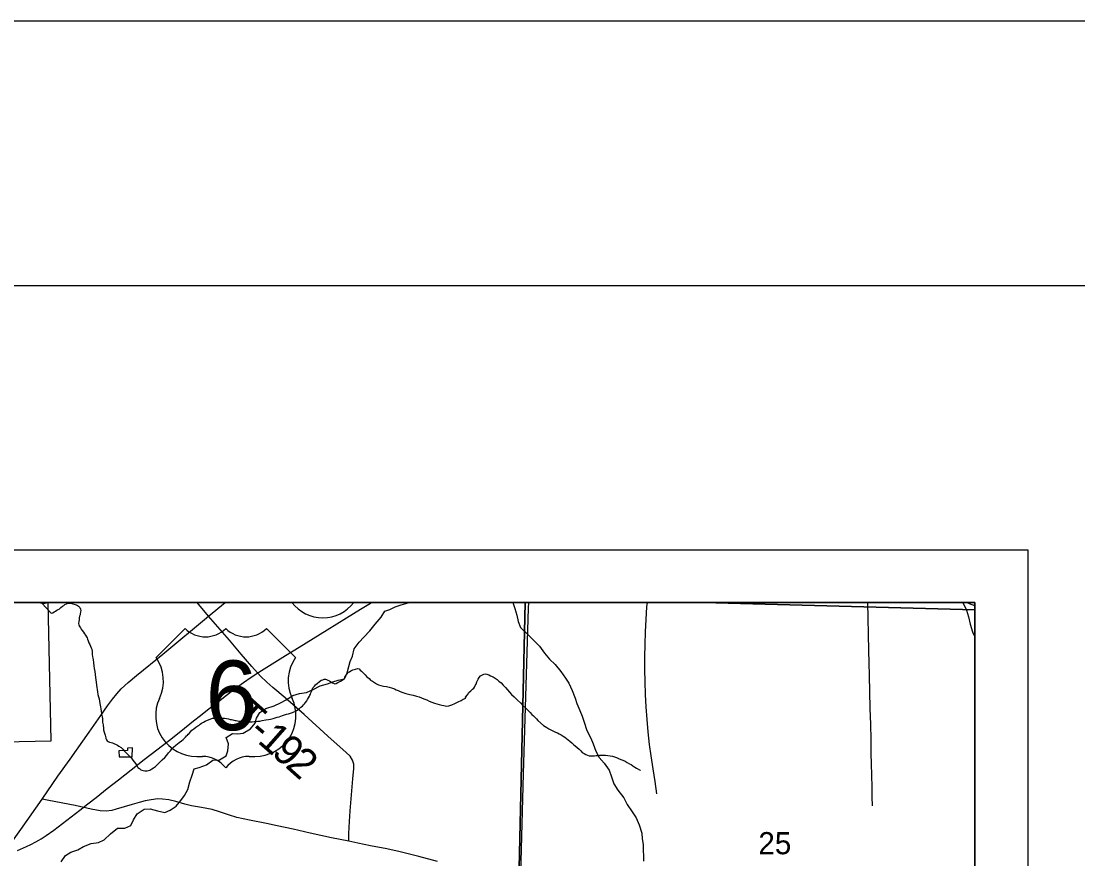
# Model space of a CAD drawing. Extents: x -6.1 to 38, y -7.7 to 22.
# Drawn here: x 7.096 to 9.095, y 20.415 to 22 of the extents above; entities that cross this region are included whole.
import ezdxf

# ---------------------------------------------------------------- set-up
doc = ezdxf.new("R2010")
doc.units = 0
for name, color, linetype in [('GM_X_Corporation', 7, 'Continuous'), ('GM_X_County_Road', 7, 'Continuous'), ('GM_X_Minor_Lake', 7, 'Continuous'), ('GM_X_Minor_River', 7, 'Continuous'), ('GM_X_Section_Text', 7, 'Continuous'), ('GM_X_Township_Road', 7, 'Continuous'), ('GM_X_Township_Road_Text', 7, 'Continuous'), ('GM_X_Unincorporated_Text', 7, 'Continuous'), ('GM_X_US_Location', 7, 'Continuous'), ('GM_X_US_Route', 7, 'Continuous'), ('GM_X_US_Shield', 7, 'Continuous'), ('SH_Border', 7, 'Continuous'), ('SH_Cut_Line', 7, 'Continuous'), ('SH_Data', 7, 'Continuous')]:
    doc.layers.add(name, color=color, linetype=linetype)

msp = doc.modelspace()

# ---------------------------------------------------------------- linework, layer by layer
at = {"layer": 'GM_X_Corporation'}
for points in [[(6.8881, 19.9366), (7.1749, 19.9235), (7.2362, 19.921), (8.0266, 19.8892), (8.0368, 20.3421), (8.0494, 20.9), (3.3101, 20.9)], [(6.9716, 20.6348), (7.153, 20.6384), (7.1472, 20.9), (4.3765, 20.9)]]:
    msp.add_lwpolyline(points, dxfattribs=at)
for points in [[(8.9, 19.5365), (8.9, 20.9), (6.9663, 20.9), (6.9744, 20.3805), (6.9756, 20.3051), (6.9766, 20.2418), (6.9774, 20.1931), (6.9933, 19.4733), (8.7731, 19.5323), (8.7757, 19.5324)], [(8.9, 19.8713), (8.9, 20.9), (8.0494, 20.9), (8.0368, 20.3421), (8.0266, 19.8892), (8.5381, 19.8802)], [(8.3868, 20.9), (8.0556, 20.9), (8.0552, 20.8892), (8.0457, 20.5759), (8.0276, 19.8894), (8.2637, 19.8849), (8.8507, 19.8735), (8.9, 19.8725), (8.9, 20.886)], [(8.9, 20.886), (8.9, 20.9), (8.3868, 20.9)]]:
    msp.add_lwpolyline(points, close=True, dxfattribs=at)
at = {"layer": 'GM_X_County_Road'}
for points in [[(7.1358, 20.5281), (7.1657, 20.5715), (7.1887, 20.6039), (7.2245, 20.6548), (7.2466, 20.6864), (7.2593, 20.7049), (7.2688, 20.717), (7.277, 20.7276), (7.2855, 20.7371), (7.2983, 20.7488), (7.314, 20.7618), (7.3639, 20.8023), (7.4505, 20.8741), (7.4822, 20.9)], [(6.7211, 20.0483), (6.7285, 20.0608), (6.7342, 20.0704), (6.7392, 20.076), (6.7582, 20.0915), (6.796, 20.1213), (6.838, 20.1539), (6.8672, 20.1774), (6.8837, 20.1917), (6.8958, 20.2039), (6.9054, 20.2146), (6.9181, 20.2305), (6.9463, 20.2673), (6.9666, 20.2941), (7.031, 20.3802), (7.0658, 20.4289), (7.0953, 20.4709), (7.1358, 20.5281)], [(7.8836, 20.41), (7.8484, 20.4198), (7.8132, 20.4287), (7.7876, 20.4341), (7.7566, 20.4401), (7.7327, 20.4446), (7.7162, 20.4484), (7.6832, 20.4552), (7.6426, 20.4637), (7.6106, 20.4711), (7.5806, 20.4774), (7.5601, 20.4818), (7.5283, 20.4881), (7.5038, 20.4933), (7.4881, 20.4983), (7.4716, 20.5043), (7.4573, 20.5084), (7.437, 20.5124), (7.4186, 20.5153), (7.4056, 20.5189), (7.3889, 20.5237), (7.3752, 20.5268), (7.3637, 20.5284), (7.3545, 20.5286), (7.3421, 20.527), (7.3309, 20.525), (7.3192, 20.5219), (7.3059, 20.5182), (7.2907, 20.5133), (7.2761, 20.5092), (7.2675, 20.5068), (7.257, 20.5052), (7.2457, 20.5061), (7.2286, 20.5092), (7.1985, 20.5158), (7.1488, 20.5254), (7.1358, 20.5281)]]:
    msp.add_lwpolyline(points, dxfattribs=at)
at = {"layer": 'GM_X_Minor_Lake'}
for points in [[(7.3067, 20.6251), (7.2976, 20.6247), (7.2973, 20.6201), (7.281, 20.6193), (7.2814, 20.6083)], [(7.2814, 20.6083), (7.306, 20.6084), (7.3067, 20.6251)]]:
    msp.add_lwpolyline(points, dxfattribs=at)
at = {"layer": 'GM_X_Minor_River'}
for points in [[(7.1318, 20.9), (7.133, 20.8997), (7.1353, 20.8989), (7.138, 20.8986), (7.1414, 20.8991), (7.1467, 20.8999), (7.147, 20.9)], [(7.1353, 20.8989), (7.1527, 20.8802), (7.1558, 20.8807), (7.1584, 20.8822), (7.161, 20.8838), (7.1637, 20.8854), (7.1663, 20.8866), (7.1682, 20.8874), (7.1715, 20.8908), (7.1742, 20.8932), (7.1768, 20.8947), (7.179, 20.8963), (7.1817, 20.8975), (7.1843, 20.8987), (7.1873, 20.8991), (7.1896, 20.8988), (7.1919, 20.8984), (7.2003, 20.8959), (7.2026, 20.8944), (7.2045, 20.8933), (7.2072, 20.8907), (7.2084, 20.8877), (7.2089, 20.8847), (7.2085, 20.8824), (7.2078, 20.8789), (7.2075, 20.8767), (7.2068, 20.8744), (7.2061, 20.8709), (7.2058, 20.8671), (7.2051, 20.8641), (7.2047, 20.8606), (7.2052, 20.858), (7.206, 20.8561), (7.2071, 20.8542), (7.2083, 20.8523), (7.2099, 20.8497), (7.2118, 20.8471), (7.2138, 20.8441), (7.2161, 20.8411), (7.2177, 20.8381), (7.22, 20.8354), (7.2208, 20.8332), (7.2216, 20.8305), (7.2232, 20.8275), (7.2244, 20.8241), (7.226, 20.8207), (7.2276, 20.8173), (7.2287, 20.8143), (7.2296, 20.8117), (7.2304, 20.8075), (7.2305, 20.8025), (7.2313, 20.7976), (7.2322, 20.7923), (7.2327, 20.7862), (7.2335, 20.7805), (7.2344, 20.7752), (7.2352, 20.7696), (7.2361, 20.7639), (7.2366, 20.7582), (7.2374, 20.754), (7.2392, 20.7396), (7.2396, 20.7358), (7.2405, 20.7312), (7.241, 20.7263), (7.2422, 20.7218), (7.2434, 20.7176), (7.2442, 20.7134), (7.2451, 20.7089), (7.2459, 20.7059), (7.2463, 20.7028), (7.2471, 20.699), (7.2476, 20.6945), (7.2481, 20.6899), (7.2489, 20.6865), (7.2493, 20.6839), (7.2498, 20.6805), (7.2498, 20.6782), (7.2502, 20.6759), (7.2503, 20.674), (7.2507, 20.6713), (7.2511, 20.6687), (7.2515, 20.6668), (7.2516, 20.6638), (7.252, 20.6619), (7.252, 20.6592), (7.2529, 20.6547), (7.2541, 20.6513), (7.2549, 20.649), (7.2557, 20.6467), (7.2561, 20.6444), (7.2565, 20.6426), (7.2573, 20.6403), (7.2589, 20.6384), (7.2608, 20.6369), (7.2635, 20.6358), (7.2665, 20.6351), (7.2688, 20.6344), (7.2715, 20.6333)], [(7.6099, 20.7243), (7.6224, 20.7281), (7.636, 20.7301), (7.6484, 20.7358), (7.662, 20.7423), (7.6753, 20.7465), (7.6858, 20.7503), (7.6957, 20.7534), (7.7078, 20.7557), (7.713, 20.7674), (7.7156, 20.7788), (7.7186, 20.7887), (7.7231, 20.7989), (7.7257, 20.8126), (7.7352, 20.8251), (7.7442, 20.8346), (7.7559, 20.8468), (7.7657, 20.8593), (7.777, 20.8723), (7.7838, 20.884), (7.7936, 20.8867), (7.8038, 20.8921), (7.8148, 20.8955), (7.8284, 20.8997), (7.8285, 20.9)], [(8.0258, 20.9), (8.0296, 20.8885), (8.0334, 20.8764), (8.0361, 20.8643), (8.0407, 20.8526), (8.0547, 20.8393), (8.0642, 20.8303), (8.0763, 20.8178), (8.0862, 20.8045), (8.0953, 20.7932), (8.1063, 20.7826), (8.1169, 20.7694), (8.1256, 20.7573), (8.1321, 20.7474), (8.1386, 20.7338), (8.1439, 20.7194), (8.1473, 20.7092), (8.1527, 20.6959), (8.1572, 20.6849), (8.1607, 20.6739), (8.166, 20.658), (8.1736, 20.6433), (8.1782, 20.6327), (8.1831, 20.6186), (8.1892, 20.6069), (8.1991, 20.5959), (8.2082, 20.5827), (8.2124, 20.5702), (8.217, 20.5573), (8.2249, 20.5448), (8.2359, 20.5308), (8.2424, 20.5183), (8.2519, 20.5043), (8.2595, 20.4926), (8.2652, 20.4793), (8.2698, 20.4638), (8.2709, 20.4528), (8.2725, 20.4426), (8.2729, 20.4312), (8.2733, 20.421), (8.273, 20.4107)], [(8.8773, 20.9), (8.8839, 20.8857), (8.8877, 20.8732), (8.8912, 20.8592), (8.8954, 20.8448), (8.9, 20.8349)], [(7.5983, 20.6886), (7.6016, 20.6898), (7.6058, 20.691), (7.6092, 20.6922), (7.6118, 20.693), (7.6145, 20.6942), (7.6224, 20.6997), (7.6254, 20.702), (7.628, 20.7043), (7.6302, 20.7066), (7.6321, 20.7086), (7.6339, 20.7109), (7.6362, 20.714), (7.638, 20.7167), (7.6395, 20.7197), (7.6413, 20.7228), (7.6424, 20.7251), (7.6435, 20.727), (7.6442, 20.7293), (7.645, 20.7316), (7.6457, 20.7335), (7.6464, 20.7358), (7.6479, 20.7389), (7.6508, 20.7416), (7.6531, 20.7443), (7.6564, 20.7474), (7.6598, 20.7501), (7.6636, 20.7529), (7.667, 20.7541), (7.6692, 20.7549), (7.6719, 20.7549), (7.6738, 20.7542), (7.6761, 20.7531), (7.6791, 20.752), (7.6811, 20.7505), (7.683, 20.7494), (7.6849, 20.7483), (7.6868, 20.7476), (7.6895, 20.7465), (7.6918, 20.7469), (7.6952, 20.7485), (7.7004, 20.7516), (7.7049, 20.7544), (7.7079, 20.7559), (7.7086, 20.759), (7.712, 20.7648), (7.7153, 20.7682), (7.7172, 20.769), (7.7198, 20.771), (7.7236, 20.7726), (7.7285, 20.7742), (7.733, 20.775), (7.7353, 20.7747), (7.7376, 20.7724), (7.74, 20.7702), (7.7431, 20.7668), (7.7465, 20.7635), (7.75, 20.7597), (7.7543, 20.7564), (7.757, 20.7534), (7.7604, 20.7512), (7.7643, 20.7486), (7.7685, 20.7464), (7.7723, 20.7445), (7.7765, 20.7431), (7.7815, 20.742), (7.7872, 20.741), (7.7922, 20.74), (7.7967, 20.7389), (7.8021, 20.7371), (7.8055, 20.7352), (7.809, 20.7338), (7.8128, 20.7316), (7.8178, 20.7298), (7.8239, 20.728), (7.8311, 20.7262), (7.8376, 20.7248), (7.8437, 20.723), (7.8487, 20.7216), (7.8533, 20.7198), (7.8579, 20.7176), (7.8632, 20.7157), (7.8678, 20.7135), (7.8732, 20.7114), (7.8782, 20.7099), (7.8824, 20.7085), (7.8869, 20.707), (7.8915, 20.706), (7.8957, 20.7053), (7.8984, 20.7046), (7.9014, 20.7043), (7.9052, 20.7047), (7.9109, 20.7063), (7.9161, 20.7091), (7.9225, 20.7122), (7.9282, 20.7146), (7.9323, 20.717), (7.9369, 20.719), (7.9368, 20.7209), (7.9402, 20.7255), (7.9431, 20.7297)], [(7.9431, 20.7297), (7.9469, 20.7328), (7.9495, 20.7359), (7.9521, 20.7382), (7.9539, 20.7402), (7.955, 20.7429), (7.9565, 20.7459), (7.958, 20.7498), (7.9594, 20.7524), (7.9605, 20.7551), (7.9624, 20.7582), (7.965, 20.7613), (7.9672, 20.7629), (7.971, 20.7644), (7.9744, 20.7649), (7.9771, 20.7646), (7.9805, 20.7631), (7.9836, 20.7612), (7.9889, 20.7594), (7.9928, 20.7568), (7.9962, 20.7542), (7.9997, 20.7513), (8.0039, 20.7479), (8.0078, 20.7438), (8.0121, 20.7393), (8.0159, 20.7352), (8.0198, 20.7307), (8.0237, 20.7258), (8.0283, 20.7214), (8.0349, 20.7154), (8.0403, 20.7102), (8.0453, 20.7053), (8.0504, 20.7005), (8.055, 20.696), (8.0589, 20.6919), (8.062, 20.6885), (8.0651, 20.6855), (8.0682, 20.6825), (8.0709, 20.6799), (8.0736, 20.6769), (8.0844, 20.6676), (8.0875, 20.6654), (8.0905, 20.6635), (8.094, 20.6613), (8.0978, 20.6591), (8.102, 20.6573), (8.1066, 20.6551), (8.1105, 20.6533), (8.1139, 20.6514), (8.1174, 20.65), (8.1216, 20.6474), (8.1247, 20.6451), (8.1277, 20.6429), (8.1308, 20.6403), (8.1339, 20.6377), (8.1374, 20.6347), (8.1409, 20.6317), (8.1443, 20.6288), (8.1478, 20.6258), (8.1513, 20.6224), (8.1547, 20.6194), (8.1575, 20.6165), (8.1613, 20.6146), (8.164, 20.6128), (8.167, 20.6113), (8.1705, 20.6102), (8.1739, 20.6099), (8.1769, 20.61), (8.1804, 20.61), (8.1834, 20.6105), (8.1864, 20.6109), (8.1898, 20.6113), (8.1929, 20.6114), (8.1974, 20.6115), (8.2012, 20.6115), (8.2058, 20.6109), (8.2104, 20.6102), (8.2146, 20.6095), (8.2184, 20.6084), (8.2222, 20.607), (8.226, 20.6051), (8.2302, 20.6033), (8.2344, 20.6019), (8.2383, 20.6), (8.2421, 20.5974), (8.2467, 20.5952), (8.2502, 20.5934), (8.2532, 20.5912), (8.2567, 20.5886), (8.2602, 20.5867), (8.2671, 20.5827), (8.2678, 20.5823)], [(7.1721, 20.4098), (7.18, 20.4216), (7.1898, 20.4277), (7.2034, 20.4323), (7.214, 20.4384), (7.2287, 20.4441), (7.2427, 20.446), (7.2529, 20.4514), (7.265, 20.4624), (7.2782, 20.4735), (7.2922, 20.4731), (7.3035, 20.4785), (7.3088, 20.4891), (7.3155, 20.5005), (7.3287, 20.5092), (7.3401, 20.5097), (7.3541, 20.5059), (7.3677, 20.5029), (7.3779, 20.5071), (7.3892, 20.5147), (7.3983, 20.5254), (7.4054, 20.5349), (7.4115, 20.5463), (7.4152, 20.5611), (7.4193, 20.5732), (7.4231, 20.5854), (7.4329, 20.5877), (7.4465, 20.593), (7.4586, 20.6018), (7.4711, 20.6026), (7.4839, 20.6098), (7.4873, 20.6193), (7.488, 20.6326), (7.4842, 20.6447), (7.4959, 20.6523), (7.5057, 20.6516), (7.5163, 20.6531), (7.5299, 20.6611), (7.5389, 20.6718), (7.5412, 20.6816), (7.5476, 20.6923), (7.5589, 20.6995), (7.5744, 20.7045), (7.5869, 20.7102), (7.5971, 20.7159), (7.6099, 20.7243)], [(7.2715, 20.6333), (7.2757, 20.6315), (7.2784, 20.63), (7.2811, 20.6285), (7.2853, 20.6256), (7.2884, 20.6226), (7.2919, 20.6192), (7.295, 20.6159), (7.3047, 20.6054), (7.3074, 20.602), (7.3097, 20.5986), (7.3124, 20.5953), (7.3148, 20.5919), (7.3171, 20.5881), (7.3198, 20.5863), (7.3225, 20.5837), (7.3244, 20.5829), (7.3271, 20.5822), (7.3298, 20.5819), (7.3324, 20.5819), (7.3347, 20.582), (7.337, 20.5824), (7.3396, 20.5832), (7.3434, 20.5852), (7.3467, 20.5875), (7.3501, 20.5899), (7.3535, 20.5933), (7.358, 20.5976), (7.3628, 20.6026), (7.3677, 20.6069), (7.3714, 20.6115), (7.3751, 20.6158), (7.3785, 20.6196), (7.3814, 20.6231), (7.3844, 20.6266), (7.3885, 20.6301), (7.3919, 20.6328), (7.3953, 20.6355), (7.3994, 20.6386), (7.4028, 20.641), (7.405, 20.6433), (7.4069, 20.6456), (7.4091, 20.6479), (7.411, 20.6491), (7.4121, 20.651), (7.4139, 20.6526), (7.4162, 20.6557), (7.4192, 20.6584), (7.4225, 20.6611), (7.4263, 20.6642), (7.43, 20.6666), (7.4327, 20.6681), (7.4349, 20.6701), (7.4375, 20.672), (7.4409, 20.674), (7.4443, 20.6759), (7.4579, 20.6811), (7.4605, 20.6816), (7.4624, 20.6816), (7.4643, 20.682), (7.4666, 20.682), (7.4689, 20.6817), (7.4708, 20.6817), (7.4727, 20.6818), (7.4753, 20.6814), (7.4784, 20.6811), (7.481, 20.6812), (7.4848, 20.6805), (7.4883, 20.6798), (7.4913, 20.6791), (7.494, 20.6787), (7.4967, 20.678), (7.4986, 20.6777), (7.5009, 20.677), (7.5031, 20.6766), (7.5054, 20.6763), (7.5077, 20.6759), (7.5096, 20.6756), (7.5119, 20.6749), (7.5161, 20.6749), (7.5191, 20.6746), (7.5225, 20.6747), (7.526, 20.6747), (7.5294, 20.6744), (7.5332, 20.6745), (7.537, 20.6749), (7.5404, 20.675), (7.5438, 20.6754), (7.5476, 20.6759), (7.5521, 20.6767), (7.5589, 20.678), (7.5639, 20.6788), (7.568, 20.6797), (7.5726, 20.6809), (7.5763, 20.6821), (7.5801, 20.6833), (7.5839, 20.6841), (7.5873, 20.6853), (7.5907, 20.6865), (7.5945, 20.6874), (7.5983, 20.6886)]]:
    msp.add_lwpolyline(points, dxfattribs=at)
at = {"layer": 'GM_X_Township_Road'}
msp.add_line((7.4505, 20.8741), (7.4293, 20.9), dxfattribs=at)
for points in [[(8.2986, 20.538), (8.295, 20.5618), (8.2916, 20.5852), (8.2875, 20.61), (8.2847, 20.6317), (8.2822, 20.6552), (8.2801, 20.6788), (8.2784, 20.7025), (8.2771, 20.7261), (8.2762, 20.7498), (8.2758, 20.7735), (8.276, 20.7972), (8.2761, 20.8209), (8.277, 20.8445), (8.2782, 20.8682), (8.2798, 20.8918), (8.2805, 20.9)], [(8.7063, 20.5153), (8.706, 20.5328), (8.7058, 20.5504), (8.705, 20.5744), (8.7046, 20.5946), (8.7041, 20.6148), (8.7036, 20.6419), (8.703, 20.6691), (8.7022, 20.7002), (8.7014, 20.7312), (8.7006, 20.7623), (8.7, 20.7858), (8.6994, 20.8093), (8.6987, 20.8404), (8.698, 20.8706), (8.6973, 20.9)], [(8.9, 20.8937), (8.8896, 20.8975), (8.8844, 20.9)], [(7.7162, 20.4484), (7.7162, 20.4629), (7.717, 20.4856), (7.7184, 20.5059), (7.721, 20.5361), (7.7232, 20.5665), (7.7252, 20.5858), (7.7252, 20.5944), (7.723, 20.6017), (7.7184, 20.6093), (7.7108, 20.6164), (7.676, 20.6474), (7.6315, 20.688), (7.5955, 20.72), (7.5721, 20.7391), (7.5609, 20.7497), (7.5486, 20.761), (7.5327, 20.7788), (7.5122, 20.8021), (7.49, 20.8288), (7.4505, 20.8741)]]:
    msp.add_lwpolyline(points, dxfattribs=at)
at = {"layer": 'GM_X_Unincorporated_Text'}
msp.add_line((7.7255, 20.9), (7.6081, 20.9), dxfattribs=at)
msp.add_arc((7.6668, 20.9457), 0.0744, 217.8737, 322.1263, dxfattribs=at)
at = {"layer": 'GM_X_US_Route'}
msp.add_lwpolyline([(7.0895, 20.431), (7.1063, 20.4387), (7.1143, 20.4426), (7.1242, 20.4475), (7.1299, 20.4504), (7.1343, 20.4531), (7.1437, 20.4595), (7.1581, 20.4696), (7.1823, 20.4882), (7.2069, 20.5072), (7.2224, 20.5193), (7.238, 20.5313), (7.259, 20.548), (7.28, 20.5647), (7.3045, 20.5838), (7.329, 20.6029), (7.3527, 20.6215), (7.3765, 20.64), (7.398, 20.657), (7.4224, 20.6763), (7.4354, 20.6866), (7.4484, 20.6968), (7.4725, 20.7156), (7.4967, 20.7344), (7.5168, 20.7491), (7.531, 20.759), (7.5458, 20.7684), (7.5706, 20.7838), (7.5962, 20.7996), (7.6219, 20.8154), (7.6483, 20.8318), (7.6747, 20.8482), (7.6931, 20.8596), (7.7114, 20.871), (7.7379, 20.8873), (7.7566, 20.8988), (7.7585, 20.9)], dxfattribs=at)
at = {"layer": 'GM_X_US_Shield'}
for p, q in [((7.4063, 20.8508), (7.3513, 20.7959)), ((7.615, 20.7959), (7.5601, 20.8508)), ((7.4282, 20.6091), (7.4392, 20.6091)), ((7.5271, 20.6091), (7.5381, 20.6091))]:
    msp.add_line(p, q, dxfattribs=at)
for centre, radius, start, end in [((7.4447, 20.8901), 0.0549, 225.573, 314.427), ((7.5216, 20.8901), 0.0549, 225.573, 314.427), ((7.2883, 20.7518), 0.0769, 334.5471, 35.0009), ((7.678, 20.7518), 0.0769, 144.9991, 205.4529), ((7.4274, 20.686), 0.0769, 154.8319, 270.6383), ((7.539, 20.686), 0.0769, 269.3617, 25.1681), ((7.4392, 20.5542), 0.0549, 36.8699, 90), ((7.5271, 20.5542), 0.0549, 90, 143.1301)]:
    msp.add_arc(centre, radius, start, end, dxfattribs=at)
at = {"layer": 'SH_Border'}
msp.add_lwpolyline([(1.5, 21.5), (33.5, 21.5), (33.5, 0.5), (1.5, 0.5)], close=True, dxfattribs=at)
at = {"layer": 'SH_Cut_Line'}
msp.add_lwpolyline([(0, 0), (34, 0), (34, 22), (0, 22)], close=True, dxfattribs=at)
at = {"layer": 'SH_Data'}
for p, q in [((2, 21), (9, 21)), ((9, 21), (9, 14)), ((2.1, 20.9), (8.9, 20.9)), ((8.9, 20.9), (8.9, 14.1))]:
    msp.add_line(p, q, dxfattribs=at)

# ---------------------------------------------------------------- texts
at = {"layer": 'GM_X_Section_Text'}
msp.add_text('25', height=0.04186, rotation=0, dxfattribs=at).set_placement((8.4905, 20.4239))
at = {"layer": 'GM_X_Township_Road_Text'}
for s, rotation, p in [('T', 318.2625, (7.491, 20.6806)), ('-', 319.5649, (7.5238, 20.6514)), ('1', 318.6305, (7.5413, 20.6364)), ('9', 318.4205, (7.5676, 20.6133)), ('2', 318.3652, (7.5937, 20.5901))]:
    msp.add_text(s, height=0.0568, rotation=rotation, dxfattribs=at).set_placement(p)
at = {"layer": 'GM_X_US_Location'}
for s in ['0', '/']:
    msp.add_text(s, height=0.000189, dxfattribs=at).set_placement((7.4831, 20.7234))
msp.add_text('6', height=0.000189, rotation=0, dxfattribs=at).set_placement((7.464, 20.6842))
at = {"layer": 'GM_X_US_Shield'}
msp.add_text('6', height=0.1318, dxfattribs=at).set_placement((7.4449, 20.6586))

doc.saveas('drawing.dxf')
